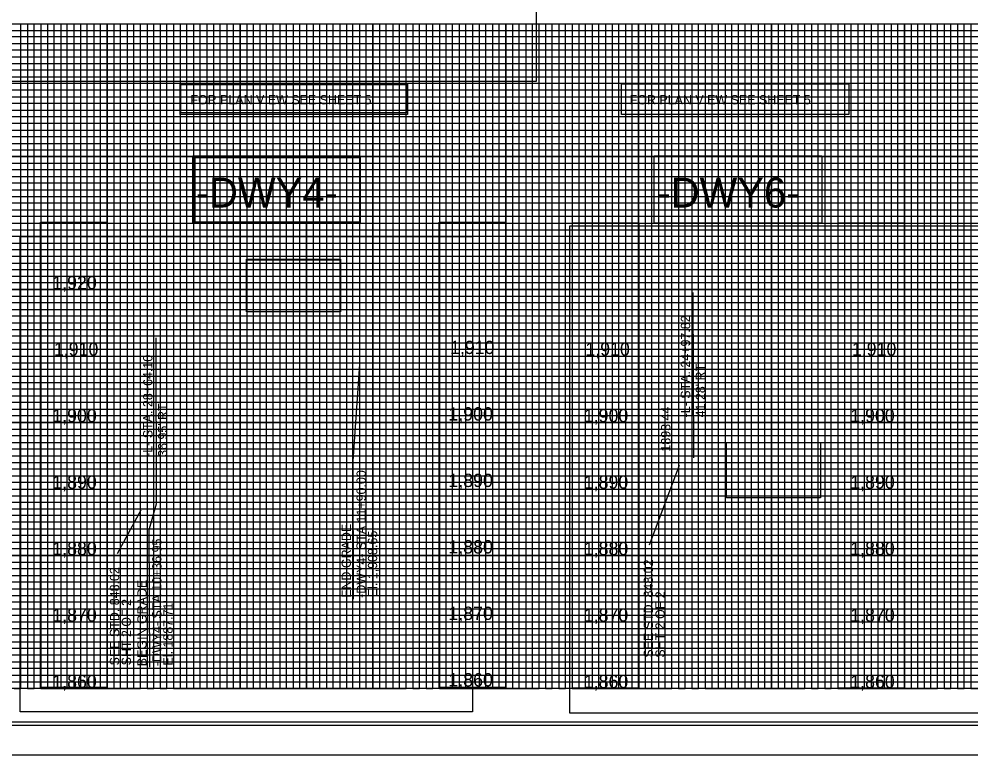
# Model space of a CAD drawing. Extents: x 557032 to 558930, y 525869 to 527437.
# Drawn here: x 557533 to 558250, y 525869 to 526423 of the extents above; entities that cross this region are included whole.
import ezdxf

# ---------------------------------------------------------------- set-up
doc = ezdxf.new("R2010")
doc.units = 0
for name, color, linetype in [('Exist Vertical Profile Vertical Axis Label', 7, 'Continuous'), ('Old_Level_63', 7, 'Continuous'), ('Prop Vertical Profile Curve Label', 7, 'Continuous'), ('Prop Vertical Profile Grade Label', 7, 'Continuous'), ('Prop VPI Label', 7, 'Continuous'), ('Raster_Level_4', 7, 'Continuous'), ('Sheet Cutting Line CELL', 7, 'Continuous'), ('Sheet DOT Grid CELL', 7, 'Continuous'), ('Sheet Layout Profile Border Port 2', 7, 'Continuous'), ('Sheet Plot Border Inside CELL', 7, 'Continuous'), ('Sheet Plot Border Outside CELL', 7, 'Continuous'), ('Sheet Profile CELL', 7, 'Continuous'), ('Sheet Profile Grid Major CELL', 7, 'Continuous'), ('Sheet Profile Grid Middle CELL', 7, 'Continuous'), ('Sheet Profile Grid Minor CELL', 7, 'Continuous')]:
    doc.layers.add(name, color=color, linetype=linetype)

msp = doc.modelspace()

# ---------------------------------------------------------------- linework, layer by layer
at = {"layer": 'Old_Level_63'}
for points in [[(557549.39, 526269.96), (557599.39, 526269.96), (557599.39, 525919.96), (557549.39, 525919.96)], [(557849.29, 526269.96), (557899.29, 526269.96), (557899.29, 525919.96), (557849.29, 525919.96)], [(557949.64, 526269.33), (557999.64, 526269.33), (557999.64, 525919.33), (557949.64, 525919.33)], [(558149.61, 526269.33), (558199.61, 526269.33), (558199.61, 525919.33), (558149.61, 525919.33)]]:
    msp.add_lwpolyline(points, close=True, dxfattribs=at)
at = {"layer": 'Prop Vertical Profile Curve Label'}
for points in [[(557665.74, 526318.61), (557789.56, 526318.61), (557789.56, 526270.04), (557665.74, 526270.04)], [(558011.23, 526319.81), (558137.2, 526319.81), (558137.2, 526269.07), (558011.23, 526269.07)], [(557704.39, 526241.66), (557774.98, 526241.66), (557774.98, 526202.5), (557704.39, 526202.5)], [(558065.64, 526104.27), (558136.27, 526104.27), (558136.27, 526062.64), (558065.64, 526062.64)]]:
    msp.add_lwpolyline(points, close=True, dxfattribs=at)
at = {"layer": 'Prop VPI Label'}
for p, q in [((558040.32, 526217.17), (558040.73, 526092.72)), ((557635.99, 526183.02), (557636.4, 526057.79)), ((557784.5, 526090.26), (557789.65, 526163.2)), ((557784.85, 525986.43), (557784.5, 526090.26)), ((558030.03, 526087.01), (558007.32, 526026.96)), ((557624.78, 526053.38), (557607.01, 526020.55)), ((557636.4, 526057.79), (557631.13, 526039.19)), ((557631.48, 525935.36), (557631.13, 526039.19))]:
    msp.add_line(p, q, dxfattribs=at)
for points in [[(557654.35, 526373.89), (557825.49, 526373.89), (557825.49, 526350.98), (557654.35, 526350.98)], [(557986.54, 526373.89), (558157.68, 526373.89), (558157.68, 526350.98), (557986.54, 526350.98)], [(557986.54, 526373.89), (558157.68, 526373.89), (558157.68, 526350.98), (557986.54, 526350.98)], [(557654.84, 526373.44), (557824.46, 526373.44), (557824.46, 526352.26), (557654.84, 526352.26)], [(557663.99, 526319.81), (557789.96, 526319.8), (557789.96, 526269.07), (557663.99, 526269.08)], [(558011.23, 526319.81), (558137.2, 526319.8), (558137.2, 526269.07), (558011.23, 526269.08)], [(557704.39, 526242.01), (557774.98, 526242.01), (557774.98, 526202.5), (557704.39, 526202.5)], [(558065.64, 526104.27), (558136.27, 526104.27), (558136.27, 526062.64), (558065.64, 526062.64)]]:
    msp.add_lwpolyline(points, close=True, dxfattribs=at)
at = {"layer": 'Raster_Level_4'}
for points in [[(557512.44, 526788.54), (557922.28, 526788.54), (557922.28, 526375.72), (557512.44, 526375.72)], [(557947.68, 526267.12), (558292.15, 526267.12), (558292.15, 525900.58), (557947.68, 525900.58)], [(557533.89, 526259.19), (557874.28, 526259.19), (557874.28, 525901.67), (557533.89, 525901.67)]]:
    msp.add_lwpolyline(points, close=True, dxfattribs=at)
at = {"layer": 'Sheet Cutting Line CELL'}
msp.add_line((557032.45, 525869.22), (558716.45, 525869.22), dxfattribs=at)
at = {"layer": 'Sheet DOT Grid CELL'}
for p, q in [((557199.45, 526419.22), (558699.34, 526419.22)), ((557549.45, 526419.22), (557549.45, 525919.22)), ((557599.45, 526419.22), (557599.45, 525919.22)), ((557649.45, 526419.22), (557649.45, 525919.22)), ((557699.45, 526419.22), (557699.45, 525919.22)), ((557749.45, 526419.22), (557749.45, 525919.22)), ((557799.45, 526419.22), (557799.45, 525919.22)), ((557849.45, 526419.22), (557849.45, 525919.22)), ((557899.45, 526419.22), (557899.45, 525919.22)), ((557949.45, 526419.22), (557949.45, 525919.22)), ((557999.45, 526419.22), (557999.45, 525919.22)), ((558049.45, 526419.22), (558049.45, 525919.22)), ((558099.45, 526419.22), (558099.45, 525919.22)), ((558149.45, 526419.22), (558149.45, 525919.22)), ((558199.45, 526419.22), (558199.45, 525919.22)), ((558249.45, 526419.22), (558249.45, 525919.22)), ((557199.45, 526319.22), (558699.34, 526319.22)), ((557199.45, 526269.22), (558699.34, 526269.22)), ((557199.45, 526219.22), (558699.34, 526219.22)), ((557199.45, 526169.22), (558699.34, 526169.22)), ((557199.45, 526119.22), (558699.34, 526119.22)), ((557199.45, 526069.22), (558699.34, 526069.22)), ((557199.45, 526019.22), (558699.34, 526019.22)), ((557199.45, 525969.22), (558699.34, 525969.22))]:
    msp.add_line(p, q, dxfattribs=at)
at = {"layer": 'Sheet Layout Profile Border Port 2'}
msp.add_lwpolyline([(557249.45, 526419.22), (558649.45, 526419.22), (558649.45, 525919.22), (557249.45, 525919.22)], close=True, dxfattribs=at)
at = {"layer": 'Sheet Plot Border Inside CELL'}
msp.add_lwpolyline([(557045.45, 525891.67), (558711.95, 525891.67), (558711.95, 526946.77), (557045.45, 526946.77)], close=True, dxfattribs=at)
at = {"layer": 'Sheet Plot Border Outside CELL'}
msp.add_lwpolyline([(557032.45, 525869.22), (558716.45, 525869.22), (558716.45, 526969.22), (557032.45, 526969.22)], close=True, dxfattribs=at)
at = {"layer": 'Sheet Profile CELL'}
for p, q in [((557199.45, 526419.22), (558699.45, 526419.22)), ((558699.45, 525919.22), (557199.45, 525919.22)), ((557199.45, 525894.22), (558699.45, 525894.22))]:
    msp.add_line(p, q, dxfattribs=at)
msp.add_lwpolyline([(558699.45, 526944.22), (557199.45, 526944.22), (557199.45, 525894.22), (558699.45, 525894.22)], close=True, dxfattribs=at)
at = {"layer": 'Sheet Profile Grid Major CELL'}
for p, q in [((557699.45, 526419.22), (557749.45, 526419.22)), ((557799.45, 526419.22), (557849.45, 526419.22)), ((557899.45, 526419.22), (557949.45, 526419.22)), ((557999.45, 526419.22), (558049.45, 526419.22)), ((558099.45, 526419.22), (558149.45, 526419.22)), ((558199.45, 526419.22), (558249.45, 526419.22)), ((557549.57, 526219.22), (557599.57, 526219.22)), ((557949.45, 526219.22), (557999.45, 526219.22)), ((557949.45, 526219.22), (557999.45, 526219.22)), ((557549.57, 526169.22), (557599.57, 526169.22)), ((557699.45, 526169.22), (557749.45, 526169.22)), ((557849.46, 526169.22), (557899.46, 526169.22)), ((557949.45, 526169.22), (557999.45, 526169.22)), ((557949.45, 526169.22), (557999.45, 526169.22)), ((557949.63, 526169.22), (557999.63, 526169.22)), ((558149.45, 526169.22), (558199.45, 526169.22)), ((557549.63, 526119.22), (557599.63, 526119.22)), ((557699.45, 526119.22), (557749.45, 526119.22)), ((557849.46, 526119.22), (557899.46, 526119.22)), ((557949.45, 526119.22), (557999.45, 526119.22)), ((557949.45, 526119.22), (557999.45, 526119.22)), ((557949.63, 526119.22), (557999.63, 526119.22)), ((558149.63, 526119.22), (558199.63, 526119.22)), ((557549.63, 526069.22), (557599.63, 526069.22)), ((557699.45, 526069.22), (557749.45, 526069.22)), ((557849.46, 526069.22), (557899.46, 526069.22)), ((557949.45, 526069.22), (557999.45, 526069.22)), ((557949.45, 526069.22), (557999.45, 526069.22)), ((557949.63, 526069.22), (557999.63, 526069.22)), ((558149.79, 526069.22), (558199.79, 526069.22)), ((557549.63, 526019.22), (557599.63, 526019.22)), ((557699.45, 526019.22), (557749.45, 526019.22)), ((557849.63, 526019.22), (557899.63, 526019.22)), ((557949.45, 526019.22), (557999.45, 526019.22)), ((557949.45, 526019.22), (557999.45, 526019.22)), ((557949.63, 526019.22), (557999.63, 526019.22)), ((558149.63, 526019.22), (558199.63, 526019.22)), ((557549.63, 525969.22), (557599.63, 525969.22)), ((557699.45, 525969.22), (557749.45, 525969.22)), ((557849.46, 525969.22), (557899.46, 525969.22)), ((557949.45, 525969.22), (557999.45, 525969.22)), ((557949.45, 525969.22), (557999.45, 525969.22)), ((557949.63, 525969.22), (557999.63, 525969.22)), ((558149.63, 525969.22), (558199.63, 525969.22))]:
    msp.add_line(p, q, dxfattribs=at)
for points in [[(557499.45, 526419.22), (557549.45, 526419.22), (557549.45, 525919.22), (557599.45, 525919.22), (557599.45, 526419.22), (557649.45, 526419.22), (557649.45, 525919.22), (557699.45, 525919.22), (557699.45, 526419.22), (557749.45, 526419.22), (557749.45, 525919.22), (557799.45, 525919.22), (557799.45, 526419.22), (557849.45, 526419.22), (557849.45, 525919.22), (557899.45, 525919.22), (557899.45, 526419.22), (557949.45, 526419.22), (557949.45, 525919.22), (557999.45, 525919.22), (557999.45, 526419.22), (558049.45, 526419.22), (558049.45, 525919.22), (558099.45, 525919.22), (558099.45, 526419.22), (558149.45, 526419.22), (558149.45, 525919.22), (558199.45, 525919.22), (558199.45, 526419.22), (558249.45, 526419.22), (558249.45, 525919.22), (558299.45, 525919.22)], [(558699.45, 526369.22), (557199.45, 526369.22)], [(558699.45, 526319.22), (557199.45, 526319.22), (557199.45, 526269.22), (558699.45, 526269.22)], [(558699.45, 526219.22), (557199.45, 526219.22), (557199.45, 526169.22), (558699.45, 526169.22)], [(558699.45, 526119.22), (557199.45, 526119.22), (557199.45, 526069.22), (558699.45, 526069.22)], [(558542.78, 526019.22), (557199.45, 526019.22), (557199.45, 526019.22), (557199.45, 525969.22), (558699.45, 525969.22)], [(558699.45, 525919.22), (557199.45, 525919.22)]]:
    msp.add_lwpolyline(points, dxfattribs=at)
for points in [[(557699.45, 525919.22), (557749.45, 525919.22), (557749.45, 526269.22), (557699.45, 526269.22)], [(557949.45, 525919.22), (557999.45, 525919.22), (557999.45, 526269.22), (557949.45, 526269.22)], [(557949.45, 525919.22), (557999.45, 525919.22), (557999.45, 526269.22), (557949.45, 526269.22)]]:
    msp.add_lwpolyline(points, close=True, dxfattribs=at)
at = {"layer": 'Sheet Profile Grid Middle CELL'}
for points in [[(557524.45, 526419.22), (557574.45, 526419.22), (557574.45, 525919.22), (557624.45, 525919.22), (557624.45, 526419.22), (557674.45, 526419.22), (557674.45, 525919.22), (557724.45, 525919.22), (557724.45, 526419.22), (557774.45, 526419.22), (557774.45, 525919.22), (557824.45, 525919.22), (557824.45, 525919.22), (557824.45, 526419.22), (557874.45, 526419.22), (557874.45, 525919.22), (557924.45, 525919.22), (557924.45, 526419.22), (557974.45, 526419.22), (557974.45, 525919.22), (558024.45, 525919.22), (558024.45, 526419.22), (558074.45, 526419.22), (558074.45, 525919.22), (558124.45, 525919.22), (558124.45, 526419.22), (558174.45, 526419.22), (558174.45, 525919.22), (558224.45, 525919.22), (558224.45, 526419.22), (558274.45, 526419.22)], [(557199.45, 526394.22), (558699.45, 526394.22)], [(558699.45, 526344.22), (557199.45, 526344.22), (557199.45, 526294.22), (558699.45, 526294.22)], [(558699.45, 526244.22), (557199.45, 526244.22), (557199.45, 526194.22), (558699.45, 526194.22)], [(558699.45, 526144.22), (557199.45, 526144.22), (557199.45, 526094.22), (558699.45, 526094.22)], [(558699.45, 526044.22), (557199.45, 526044.22), (557199.45, 525994.22), (558699.45, 525994.22)], [(558699.45, 525944.22), (557199.45, 525944.22)]]:
    msp.add_lwpolyline(points, dxfattribs=at)
at = {"layer": 'Sheet Profile Grid Minor CELL'}
for p, q in [((557249.45, 526414.22), (558649.45, 526414.22)), ((558649.45, 526409.22), (557249.45, 526409.22)), ((557249.45, 526404.22), (558649.45, 526404.22)), ((558649.45, 526399.22), (557249.45, 526399.22)), ((557249.45, 526389.22), (558649.45, 526389.22)), ((558649.45, 526384.22), (557249.45, 526384.22)), ((557249.45, 526379.22), (558649.45, 526379.22)), ((558649.45, 526374.22), (557249.45, 526374.22)), ((557249.45, 526364.22), (558649.45, 526364.22)), ((558649.45, 526359.22), (557249.45, 526359.22)), ((557249.45, 526354.22), (558649.45, 526354.22)), ((558649.45, 526349.22), (557249.45, 526349.22)), ((557249.45, 526339.22), (558649.45, 526339.22)), ((558649.45, 526334.22), (557249.45, 526334.22)), ((557249.45, 526329.22), (558649.45, 526329.22)), ((558649.45, 526324.22), (557249.45, 526324.22)), ((557249.45, 526314.22), (558649.45, 526314.22)), ((558649.45, 526309.22), (557249.45, 526309.22)), ((557249.45, 526304.22), (558649.45, 526304.22)), ((558649.45, 526299.22), (557249.45, 526299.22)), ((557249.45, 526289.22), (558649.45, 526289.22)), ((558649.45, 526284.22), (557249.45, 526284.22)), ((557249.45, 526279.22), (558649.45, 526279.22)), ((558649.45, 526274.22), (557249.45, 526274.22)), ((557249.45, 526264.22), (558649.45, 526264.22)), ((558649.45, 526259.22), (557249.45, 526259.22)), ((557249.45, 526254.22), (558649.45, 526254.22)), ((558649.45, 526249.22), (557249.45, 526249.22)), ((557249.45, 526239.22), (558649.45, 526239.22)), ((558649.45, 526234.22), (557249.45, 526234.22)), ((557249.45, 526229.22), (558649.45, 526229.22)), ((558649.45, 526224.22), (557249.45, 526224.37)), ((557249.45, 526214.22), (558649.45, 526214.22)), ((558649.45, 526209.22), (557249.45, 526209.22)), ((557249.45, 526204.22), (558649.45, 526204.22)), ((558649.45, 526199.22), (557249.45, 526199.22)), ((557249.45, 526189.22), (558649.45, 526189.22)), ((558649.45, 526184.22), (557249.45, 526184.22)), ((557249.45, 526179.22), (558649.45, 526179.22)), ((558649.45, 526174.22), (557249.45, 526174.22)), ((557249.45, 526164.22), (558649.45, 526164.22)), ((558649.45, 526159.22), (557249.45, 526159.22)), ((557249.45, 526154.22), (558649.45, 526154.22)), ((558649.45, 526149.22), (557249.45, 526149.22)), ((557249.45, 526139.22), (558649.45, 526139.22)), ((558649.45, 526134.22), (557249.45, 526134.22)), ((557249.45, 526129.22), (558649.45, 526129.22)), ((558649.45, 526124.22), (557249.45, 526124.22)), ((557249.45, 526114.22), (558649.45, 526114.22)), ((558649.45, 526109.22), (557249.45, 526109.22)), ((557249.45, 526104.22), (558649.45, 526104.22)), ((558649.45, 526099.22), (557249.45, 526099.22)), ((557249.45, 526089.22), (558649.45, 526089.22)), ((558649.45, 526084.22), (557249.45, 526084.22)), ((557249.45, 526079.22), (558649.45, 526079.22)), ((558649.45, 526074.22), (557249.45, 526074.22)), ((557249.45, 526064.22), (558649.45, 526064.22)), ((558649.45, 526059.22), (557249.45, 526059.22)), ((557249.45, 526054.22), (558649.45, 526054.22)), ((558649.45, 526049.22), (557249.45, 526049.22)), ((557249.45, 526039.22), (558542.78, 526039.22)), ((558542.78, 526034.22), (557249.45, 526034.22)), ((557249.45, 526029.22), (558542.78, 526029.22)), ((558542.78, 526024.22), (557249.45, 526024.22)), ((557249.45, 526014.22), (558649.45, 526014.22)), ((558649.45, 526009.22), (557249.45, 526009.22)), ((557249.45, 526004.22), (558649.45, 526004.22)), ((558649.45, 525999.22), (557249.45, 525999.22)), ((557249.45, 525989.22), (558649.45, 525989.22)), ((558649.45, 525984.22), (557249.45, 525984.22)), ((557249.45, 525979.22), (558649.45, 525979.22)), ((558649.45, 525974.22), (557249.45, 525974.22)), ((557249.45, 525964.22), (558649.45, 525964.22)), ((558649.45, 525959.22), (557249.45, 525959.22)), ((557249.45, 525954.22), (558649.45, 525954.22)), ((558649.45, 525949.22), (557249.45, 525949.22)), ((557249.45, 525939.22), (558649.45, 525939.22)), ((558649.45, 525934.22), (557249.45, 525934.22)), ((557249.45, 525929.22), (558649.45, 525929.22)), ((557249.45, 525924.22), (558649.45, 525924.22))]:
    msp.add_line(p, q, dxfattribs=at)
for points in [[(557529.45, 525919.22), (557534.45, 525919.22), (557534.45, 526419.22), (557539.45, 526419.22), (557539.45, 525919.22), (557544.45, 525919.22), (557544.45, 526419.22), (557554.45, 526419.22), (557554.45, 525919.22), (557559.45, 525919.22), (557559.45, 526419.22), (557564.45, 526419.22), (557564.45, 525919.22), (557569.45, 525919.22), (557569.45, 526419.22), (557579.45, 526419.22), (557579.45, 525919.22), (557584.45, 525919.22), (557584.45, 526419.22), (557589.45, 526419.22), (557589.45, 525919.22), (557594.45, 525919.22), (557594.45, 526419.22), (557604.45, 526419.22), (557604.45, 525919.22), (557609.45, 525919.22), (557609.45, 526419.22), (557614.45, 526419.22), (557614.45, 525919.22), (557619.45, 525919.22), (557619.45, 526419.22), (557629.45, 526419.22), (557629.45, 525919.22), (557634.45, 525919.22), (557634.45, 526419.22), (557639.45, 526419.22), (557639.45, 525919.22), (557644.45, 525919.22), (557644.45, 526419.22), (557654.45, 526419.22), (557654.45, 525919.22), (557659.45, 525919.22), (557659.45, 526419.22), (557664.45, 526419.22), (557664.45, 525919.22), (557669.45, 525919.22), (557669.45, 526419.22), (557679.45, 526419.22), (557679.45, 525919.22), (557684.45, 525919.22), (557684.45, 526419.22), (557689.45, 526419.22), (557689.45, 525919.22), (557694.45, 525919.22), (557694.45, 526419.22), (557704.45, 526419.22), (557704.45, 525919.22), (557709.45, 525919.22), (557709.45, 526419.22), (557714.45, 526419.22), (557714.45, 525919.22), (557719.45, 525919.22), (557719.45, 526419.22), (557729.45, 526419.22), (557729.45, 525919.22), (557734.45, 525919.22), (557734.45, 526419.22), (557739.45, 526419.22), (557739.45, 525919.22), (557744.45, 525919.22), (557744.45, 526419.22), (557754.45, 526419.22), (557754.45, 525919.22), (557759.45, 525919.22), (557759.45, 526419.22), (557764.45, 526419.22), (557764.45, 525919.22), (557769.45, 525919.22), (557769.45, 526419.22), (557779.45, 526419.22)], [(557779.45, 526419.22), (557779.45, 525919.22), (557784.45, 525919.22), (557784.45, 526419.22), (557789.45, 526419.22), (557789.45, 525919.22), (557794.45, 525919.22), (557794.45, 526419.22), (557804.45, 526419.22), (557804.45, 525919.22), (557809.45, 525919.22), (557809.45, 526419.22), (557814.45, 526419.22), (557814.45, 525919.22), (557819.45, 525919.22), (557819.45, 526419.22), (557829.45, 526419.22), (557829.45, 525919.22), (557834.45, 525919.22), (557834.45, 526419.22), (557839.45, 526419.22), (557839.45, 525919.22), (557844.45, 525919.22), (557844.45, 526419.22), (557854.45, 526419.22), (557854.45, 525919.22), (557859.45, 525919.22), (557859.45, 526419.22), (557864.45, 526419.22), (557864.45, 525919.22), (557869.45, 525919.22), (557869.45, 526419.22), (557879.45, 526419.22), (557879.45, 525919.22), (557884.45, 525919.22), (557884.45, 526419.22), (557889.45, 526419.22), (557889.45, 525919.22), (557894.45, 525919.22), (557894.45, 526419.22), (557904.45, 526419.22), (557904.45, 525919.22), (557904.45, 525919.22), (557909.45, 525919.22), (557909.45, 526419.22), (557914.45, 526419.22), (557914.45, 525919.22), (557919.45, 525919.22), (557919.45, 526419.22), (557929.45, 526419.22), (557929.45, 525919.22), (557934.45, 525919.22), (557934.45, 526419.22), (557939.45, 526419.22), (557939.45, 525919.22), (557944.45, 525919.22), (557944.45, 526419.22), (557954.45, 526419.22), (557954.45, 525919.22), (557959.45, 525919.22), (557959.45, 526419.22), (557964.45, 526419.22), (557964.45, 525919.22), (557969.45, 525919.22), (557969.45, 526419.22), (557979.45, 526419.22), (557979.45, 525919.22), (557984.45, 525919.22), (557984.45, 526419.22), (557989.45, 526419.22), (557989.45, 525919.22), (557994.45, 525919.22), (557994.45, 526419.22), (558004.45, 526419.22), (558004.45, 525919.22), (558009.45, 525919.22), (558009.45, 526419.22), (558014.45, 526419.22), (558014.45, 525919.22), (558019.45, 525919.22), (558019.45, 526419.22), (558029.45, 526419.22), (558029.45, 525919.22), (558034.45, 525919.22), (558034.45, 526419.22), (558039.45, 526419.22), (558039.45, 525919.22), (558044.45, 525919.22), (558044.45, 526419.22), (558054.45, 526419.22), (558054.45, 525919.22), (558059.15, 525919.77), (558059.45, 525919.22), (558059.45, 526419.22), (558064.45, 526419.22), (558064.45, 525919.22), (558069.45, 525919.22), (558069.45, 526419.22), (558079.45, 526419.22), (558079.45, 525919.22), (558084.45, 525919.22)], [(558084.45, 525919.22), (558084.45, 526419.22), (558089.45, 526419.22), (558089.45, 525919.22), (558094.45, 525919.22), (558094.45, 526419.22), (558104.45, 526419.22), (558104.45, 525919.22), (558109.45, 525919.22), (558109.45, 526419.22), (558114.45, 526419.22), (558114.45, 525919.22), (558119.45, 525919.22), (558119.45, 526419.22), (558129.45, 526419.22), (558129.45, 525919.22), (558134.45, 525919.22), (558134.45, 526419.22), (558139.45, 526419.22), (558139.45, 525919.22), (558144.45, 525919.22), (558144.45, 526419.22), (558154.45, 526419.22), (558154.45, 525919.22), (558159.45, 525919.22), (558159.45, 526419.22), (558164.45, 526419.22), (558164.45, 525919.22), (558169.45, 525919.22), (558169.45, 526419.22), (558179.45, 526419.22), (558179.45, 525919.22), (558184.45, 525919.22), (558184.45, 526419.22), (558189.45, 526419.22), (558189.45, 525919.22), (558194.45, 525919.22), (558194.45, 526419.22), (558204.45, 526419.22), (558204.45, 525919.22), (558209.45, 525919.22), (558209.45, 526419.22), (558214.45, 526419.22), (558214.45, 525919.22), (558219.45, 525919.22), (558219.45, 526419.22), (558229.45, 526419.22), (558229.45, 525919.22), (558234.45, 525919.22), (558234.45, 526419.22), (558239.45, 526419.22), (558239.45, 525919.22), (558244.45, 525919.22), (558244.45, 526419.22), (558254.45, 526419.22)]]:
    msp.add_lwpolyline(points, dxfattribs=at)

# ---------------------------------------------------------------- texts
at = {"layer": 'Exist Vertical Profile Vertical Axis Label'}
for s, p in [('1,920', (557558.15, 526219.47)), ('1,910', (557857.49, 526170.75)), ('1,910', (557559.35, 526169.47)), ('1,910', (557959.35, 526169.47)), ('1,910', (558159.91, 526169.47)), ('1,900', (557856.29, 526120.75)), ('1,900', (557558.15, 526119.47)), ('1,900', (557958.15, 526119.47)), ('1,900', (558158.71, 526119.47)), ('1,890', (557856.29, 526070.75)), ('1,890', (557558.15, 526069.47)), ('1,890', (557958.15, 526069.47)), ('1,890', (558158.71, 526069.47)), ('1,880', (557856.29, 526020.75)), ('1,880', (557558.15, 526019.47)), ('1,880', (557958.15, 526019.47)), ('1,880', (558158.71, 526019.47)), ('1,870', (557856.29, 525970.75)), ('1,870', (557558.15, 525969.47)), ('1,870', (557958.15, 525969.47)), ('1,870', (558158.71, 525969.47)), ('1,860', (557558.15, 525919.47)), ('1,860', (557856.29, 525920.75)), ('1,860', (557958.15, 525919.47)), ('1,860', (558158.71, 525919.47))]:
    msp.add_text(s, height=10, dxfattribs=at).set_placement(p)
at = {"layer": 'Prop Vertical Profile Grade Label'}
for s, p in [('-DWY4-', (557666.1, 526280.95)), ('-DWY6-', (558013.51, 526280.95))]:
    msp.add_text(s, height=22.5, dxfattribs=at).set_placement(p)
at = {"layer": 'Prop VPI Label'}
for p in [(557662.1, 526358.53), (557992.72, 526358.53)]:
    msp.add_text('FOR PLAN VIEW SEE SHEET 5', height=7, dxfattribs=at).set_placement(p)
for s, p in [('-L- STA. 24+97.82', (558038.21, 526123.11)), ('-L- STA. 28+64.10', (557633.51, 526093.43)), ("41.28' RT", (558049.41, 526123.11)), ("36.95' RT", (557644.71, 526093.43)), ('1893.44', (558023.33, 526097.37)), ('-DWY4- STA 11+90.00', (557794.1, 525987.4)), ('END GRADE', (557782.9, 525987.4)), ('El. 1,908.65', (557802.66, 525987.91)), ('-DWY4- STA 10+36.95', (557640.33, 525935.96)), ('SEE STD. 848.02 ', (558010.23, 525942.38)), ('SEE STD. 848.02 ', (557608.5, 525936.57)), ('BEGIN GRADE', (557629.13, 525935.96)), ('SHT 2 OF 2', (558019.1, 525942.38)), ('SHT 2 OF 2', (557617.37, 525936.57)), ("El. 1887.71'", (557648.69, 525936.46))]:
    msp.add_text(s, height=7, rotation=90, dxfattribs=at).set_placement(p)

doc.saveas('drawing.dxf')
